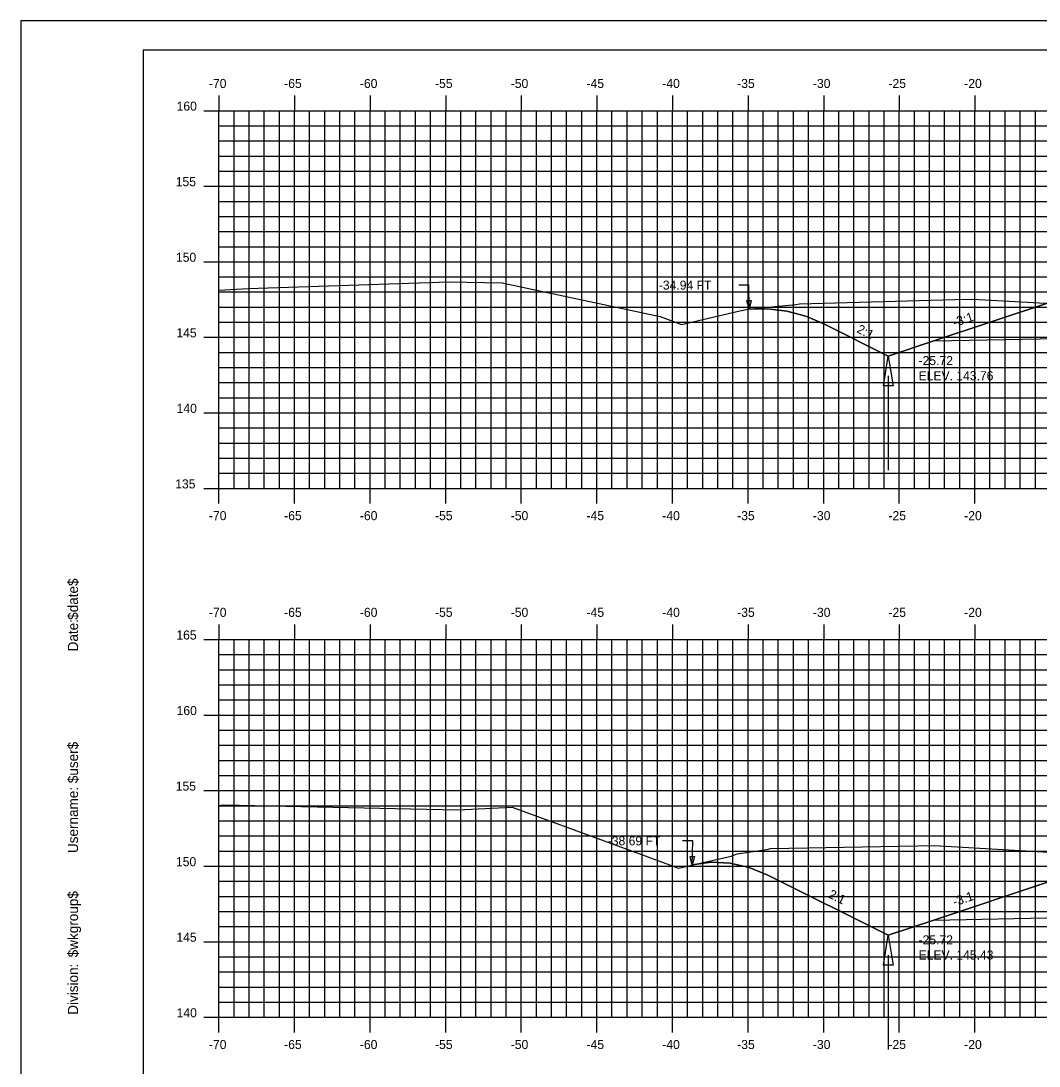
# Model space of a CAD drawing. Extents: x 1143642 to 1143812, y 608981 to 609091.
# Drawn here: x 1143641.7 to 1143709.1, y 609022.1 to 609091.3 of the extents above; entities that cross this region are included whole.
import ezdxf

# ---------------------------------------------------------------- set-up
doc = ezdxf.new("R2010")
doc.units = 0
for name, color, linetype in [('ANNOTATION', 7, 'Continuous'), ('BORDER', 7, 'Continuous'), ('D_Drainage_Ditch_Line', 7, 'Continuous'), ('D_Roadway_SlopeLines', 7, 'Continuous'), ('D_Roadway_SubGrade', 7, 'Continuous'), ('D_Text_Standard', 7, 'Continuous'), ('H_V ANNOTATION', 7, 'Continuous'), ('MAJOR', 7, 'Continuous'), ('MINOR', 7, 'Continuous'), ('PLOT BOUNDARY', 7, 'Continuous'), ('S_Roadway_Centerline', 7, 'Continuous')]:
    doc.layers.add(name, color=color, linetype=linetype)

msp = doc.modelspace()

# ---------------------------------------------------------------- linework, layer by layer
for points in [[(1143689.9, 609072.198), (1143691.15, 609072.231), (1143692.4, 609072.077), (1143693.65, 609071.734), (1143694.9, 609071.203), (1143699.112, 609069.097), (1143702.112, 609070.097), (1143709.835, 609072.671), (1143709.836, 609072.671), (1143713.836, 609072.831), (1143724.836, 609073.051), (1143735.836, 609072.831), (1143742.836, 609072.551), (1143750.368, 609070.041), (1143753.368, 609069.041), (1143766.479, 609075.596), (1143767.729, 609076.147), (1143768.979, 609076.547), (1143770.229, 609076.799), (1143771.479, 609076.901)], [(1143686.147, 609035.418), (1143687.397, 609035.592), (1143688.647, 609035.538), (1143689.897, 609035.255), (1143691.147, 609034.744), (1143699.112, 609030.762), (1143702.112, 609031.762), (1143709.835, 609034.336), (1143709.836, 609034.336), (1143713.836, 609034.496), (1143724.836, 609034.716), (1143735.836, 609034.496), (1143748.494, 609033.99), (1143755.665, 609031.599), (1143758.665, 609030.599), (1143776.249, 609039.391), (1143777.499, 609039.941), (1143778.749, 609040.338), (1143779.999, 609040.585), (1143781.249, 609040.679)]]:
    msp.add_lwpolyline(points)
at = {"layer": 'BORDER'}
msp.add_lwpolyline([(1143649.836, 608984.335), (1143809.836, 608984.335), (1143809.836, 609089.335), (1143649.836, 609089.335)], close=True, dxfattribs=at)
at = {"layer": 'D_Drainage_Ditch_Line'}
for p, q in [((1143699.112, 609067.785), (1143699.111, 609061.541)), ((1143699.112, 609029.449), (1143699.111, 609023.206))]:
    msp.add_line(p, q, dxfattribs=at)
for points in [[(1143699.44, 609067.128), (1143698.783, 609067.128), (1143699.112, 609069.097)], [(1143699.44, 609028.793), (1143698.783, 609028.793), (1143699.112, 609030.762)]]:
    msp.add_lwpolyline(points, close=True, dxfattribs=at)
at = {"layer": 'D_Roadway_SlopeLines'}
for points in [[(1143699.112, 609069.097), (1143694.9, 609071.203), (1143693.65, 609071.734), (1143692.4, 609072.077), (1143691.15, 609072.231), (1143689.9, 609072.198)], [(1143702.112, 609070.097), (1143699.112, 609069.097)], [(1143699.112, 609030.762), (1143691.147, 609034.744), (1143689.897, 609035.255), (1143688.647, 609035.538), (1143687.397, 609035.592), (1143686.147, 609035.418)], [(1143702.112, 609031.762), (1143699.112, 609030.762)]]:
    msp.add_lwpolyline(points, dxfattribs=at)
at = {"layer": 'D_Roadway_SubGrade'}
for points in [[(1143713.836, 609072.415), (1143713.836, 609072.581), (1143709.836, 609072.421), (1143709.836, 609072.671), (1143709.835, 609072.671), (1143702.112, 609070.097), (1143713.836, 609070.331)], [(1143713.836, 609034.079), (1143713.836, 609034.246), (1143709.836, 609034.086), (1143709.836, 609034.336), (1143709.835, 609034.336), (1143702.112, 609031.762), (1143713.836, 609031.996)]]:
    msp.add_lwpolyline(points, close=True, dxfattribs=at)
at = {"layer": 'D_Text_Standard'}
for points in [[(1143689.9, 609072.2), (1143689.896, 609073.789), (1143689.216, 609073.789)], [(1143686.147, 609035.397), (1143686.175, 609037.012), (1143685.495, 609037.012)]]:
    msp.add_lwpolyline(points, dxfattribs=at)
for points in [[(1143689.9, 609072.2), (1143689.753, 609072.782), (1143690.044, 609072.783)], [(1143686.147, 609035.397), (1143686.011, 609035.982), (1143686.302, 609035.977)]]:
    msp.add_lwpolyline(points, close=True, dxfattribs=at)
at = {"layer": 'MAJOR'}
for p, q in [((1143654.836, 609086.337), (1143654.836, 609085.335)), ((1143659.836, 609086.337), (1143659.836, 609085.335)), ((1143664.836, 609086.337), (1143664.836, 609085.335)), ((1143669.836, 609086.337), (1143669.836, 609085.335)), ((1143674.836, 609086.337), (1143674.836, 609085.335)), ((1143679.836, 609086.337), (1143679.836, 609085.335)), ((1143684.836, 609086.337), (1143684.836, 609085.335)), ((1143689.836, 609086.337), (1143689.836, 609085.335)), ((1143694.836, 609086.337), (1143694.836, 609085.335)), ((1143699.836, 609086.337), (1143699.836, 609085.335)), ((1143704.836, 609086.337), (1143704.836, 609085.335)), ((1143653.834, 609085.335), (1143654.836, 609085.335)), ((1143654.836, 609085.335), (1143794.836, 609085.335)), ((1143654.836, 609060.335), (1143654.836, 609085.335)), ((1143654.836, 609060.335), (1143654.836, 609085.335)), ((1143654.836, 609085.335), (1143794.836, 609085.335)), ((1143659.836, 609060.335), (1143659.836, 609085.335)), ((1143664.836, 609060.335), (1143664.836, 609085.335)), ((1143669.836, 609060.335), (1143669.836, 609085.335)), ((1143674.836, 609060.335), (1143674.836, 609085.335)), ((1143679.836, 609060.335), (1143679.836, 609085.335)), ((1143684.836, 609060.335), (1143684.836, 609085.335)), ((1143689.836, 609060.335), (1143689.836, 609085.335)), ((1143694.836, 609060.335), (1143694.836, 609085.335)), ((1143699.836, 609060.335), (1143699.836, 609085.335)), ((1143704.836, 609060.335), (1143704.836, 609085.335)), ((1143653.834, 609080.335), (1143654.836, 609080.335)), ((1143654.836, 609080.335), (1143794.836, 609080.335)), ((1143653.834, 609075.335), (1143654.836, 609075.335)), ((1143654.836, 609075.335), (1143794.836, 609075.335)), ((1143653.834, 609070.335), (1143654.836, 609070.335)), ((1143654.836, 609070.335), (1143794.836, 609070.335)), ((1143653.834, 609065.335), (1143654.836, 609065.335)), ((1143654.836, 609065.335), (1143794.836, 609065.335)), ((1143653.834, 609060.335), (1143654.836, 609060.335)), ((1143654.836, 609060.335), (1143794.836, 609060.335)), ((1143654.836, 609060.335), (1143794.836, 609060.335)), ((1143654.836, 609059.333), (1143654.836, 609060.335)), ((1143659.836, 609059.333), (1143659.836, 609060.335)), ((1143664.836, 609059.333), (1143664.836, 609060.335)), ((1143669.836, 609059.333), (1143669.836, 609060.335)), ((1143674.836, 609059.333), (1143674.836, 609060.335)), ((1143679.836, 609059.333), (1143679.836, 609060.335)), ((1143684.836, 609059.333), (1143684.836, 609060.335)), ((1143689.836, 609059.333), (1143689.836, 609060.335)), ((1143694.836, 609059.333), (1143694.836, 609060.335)), ((1143699.836, 609059.333), (1143699.836, 609060.335)), ((1143704.836, 609059.333), (1143704.836, 609060.335)), ((1143654.836, 609051.337), (1143654.836, 609050.335)), ((1143659.836, 609051.337), (1143659.836, 609050.335)), ((1143664.836, 609051.337), (1143664.836, 609050.335)), ((1143669.836, 609051.337), (1143669.836, 609050.335)), ((1143674.836, 609051.337), (1143674.836, 609050.335)), ((1143679.836, 609051.337), (1143679.836, 609050.335)), ((1143684.836, 609051.337), (1143684.836, 609050.335)), ((1143689.836, 609051.337), (1143689.836, 609050.335)), ((1143694.836, 609051.337), (1143694.836, 609050.335)), ((1143699.836, 609051.337), (1143699.836, 609050.335)), ((1143704.836, 609051.337), (1143704.836, 609050.335)), ((1143653.834, 609050.335), (1143654.836, 609050.335)), ((1143654.836, 609050.335), (1143794.836, 609050.335)), ((1143654.836, 609025.335), (1143654.836, 609050.335)), ((1143654.836, 609025.335), (1143654.836, 609050.335)), ((1143654.836, 609050.335), (1143794.836, 609050.335)), ((1143659.836, 609025.335), (1143659.836, 609050.335)), ((1143664.836, 609025.335), (1143664.836, 609050.335)), ((1143669.836, 609025.335), (1143669.836, 609050.335)), ((1143674.836, 609025.335), (1143674.836, 609050.335)), ((1143679.836, 609025.335), (1143679.836, 609050.335)), ((1143684.836, 609025.335), (1143684.836, 609050.335)), ((1143689.836, 609025.335), (1143689.836, 609050.335)), ((1143694.836, 609025.335), (1143694.836, 609050.335)), ((1143699.836, 609025.335), (1143699.836, 609050.335)), ((1143704.836, 609025.335), (1143704.836, 609050.335)), ((1143653.834, 609045.335), (1143654.836, 609045.335)), ((1143654.836, 609045.335), (1143794.836, 609045.335)), ((1143653.834, 609040.335), (1143654.836, 609040.335)), ((1143654.836, 609040.335), (1143794.836, 609040.335)), ((1143653.834, 609035.335), (1143654.836, 609035.335)), ((1143654.836, 609035.335), (1143794.836, 609035.335)), ((1143653.834, 609030.335), (1143654.836, 609030.335)), ((1143654.836, 609030.335), (1143794.836, 609030.335)), ((1143653.834, 609025.335), (1143654.836, 609025.335)), ((1143654.836, 609025.335), (1143794.836, 609025.335)), ((1143654.836, 609025.335), (1143794.836, 609025.335)), ((1143654.836, 609024.333), (1143654.836, 609025.335)), ((1143659.836, 609024.333), (1143659.836, 609025.335)), ((1143664.836, 609024.333), (1143664.836, 609025.335)), ((1143669.836, 609024.333), (1143669.836, 609025.335)), ((1143674.836, 609024.333), (1143674.836, 609025.335)), ((1143679.836, 609024.333), (1143679.836, 609025.335)), ((1143684.836, 609024.333), (1143684.836, 609025.335)), ((1143689.836, 609024.333), (1143689.836, 609025.335)), ((1143694.836, 609024.333), (1143694.836, 609025.335)), ((1143699.836, 609024.333), (1143699.836, 609025.335)), ((1143704.836, 609024.333), (1143704.836, 609025.335))]:
    msp.add_line(p, q, dxfattribs=at)
at = {"layer": 'MINOR'}
for p, q in [((1143655.836, 609060.335), (1143655.836, 609085.335)), ((1143656.836, 609060.335), (1143656.836, 609085.335)), ((1143657.836, 609060.335), (1143657.836, 609085.335)), ((1143658.836, 609060.335), (1143658.836, 609085.335)), ((1143660.836, 609060.335), (1143660.836, 609085.335)), ((1143661.836, 609060.335), (1143661.836, 609085.335)), ((1143662.836, 609060.335), (1143662.836, 609085.335)), ((1143663.836, 609060.335), (1143663.836, 609085.335)), ((1143665.836, 609060.335), (1143665.836, 609085.335)), ((1143666.836, 609060.335), (1143666.836, 609085.335)), ((1143667.836, 609060.335), (1143667.836, 609085.335)), ((1143668.836, 609060.335), (1143668.836, 609085.335)), ((1143670.836, 609060.335), (1143670.836, 609085.335)), ((1143671.836, 609060.335), (1143671.836, 609085.335)), ((1143672.836, 609060.335), (1143672.836, 609085.335)), ((1143673.836, 609060.335), (1143673.836, 609085.335)), ((1143675.836, 609060.335), (1143675.836, 609085.335)), ((1143676.836, 609060.335), (1143676.836, 609085.335)), ((1143677.836, 609060.335), (1143677.836, 609085.335)), ((1143678.836, 609060.335), (1143678.836, 609085.335)), ((1143680.836, 609060.335), (1143680.836, 609085.335)), ((1143681.836, 609060.335), (1143681.836, 609085.335)), ((1143682.836, 609060.335), (1143682.836, 609085.335)), ((1143683.836, 609060.335), (1143683.836, 609085.335)), ((1143685.836, 609060.335), (1143685.836, 609085.335)), ((1143686.836, 609060.335), (1143686.836, 609085.335)), ((1143687.836, 609060.335), (1143687.836, 609085.335)), ((1143688.836, 609060.335), (1143688.836, 609085.335)), ((1143690.836, 609060.335), (1143690.836, 609085.335)), ((1143691.836, 609060.335), (1143691.836, 609085.335)), ((1143692.836, 609060.335), (1143692.836, 609085.335)), ((1143693.836, 609060.335), (1143693.836, 609085.335)), ((1143695.836, 609060.335), (1143695.836, 609085.335)), ((1143696.836, 609060.335), (1143696.836, 609085.335)), ((1143697.836, 609060.335), (1143697.836, 609085.335)), ((1143698.836, 609060.335), (1143698.836, 609085.335)), ((1143700.836, 609060.335), (1143700.836, 609085.335)), ((1143701.836, 609060.335), (1143701.836, 609085.335)), ((1143702.836, 609060.335), (1143702.836, 609085.335)), ((1143703.836, 609060.335), (1143703.836, 609085.335)), ((1143705.836, 609060.335), (1143705.836, 609085.335)), ((1143706.836, 609060.335), (1143706.836, 609085.335)), ((1143707.836, 609060.335), (1143707.836, 609085.335)), ((1143708.836, 609060.335), (1143708.836, 609085.335)), ((1143654.836, 609084.335), (1143794.836, 609084.335)), ((1143654.836, 609084.335), (1143655.838, 609084.335)), ((1143654.836, 609083.335), (1143794.836, 609083.335)), ((1143654.836, 609083.335), (1143655.838, 609083.335)), ((1143654.836, 609082.335), (1143794.836, 609082.335)), ((1143654.836, 609082.335), (1143655.838, 609082.335)), ((1143654.836, 609081.335), (1143794.836, 609081.335)), ((1143654.836, 609081.335), (1143655.838, 609081.335)), ((1143654.836, 609079.335), (1143794.836, 609079.335)), ((1143654.836, 609079.335), (1143655.838, 609079.335)), ((1143654.836, 609078.335), (1143794.836, 609078.335)), ((1143654.836, 609078.335), (1143655.838, 609078.335)), ((1143654.836, 609077.335), (1143794.836, 609077.335)), ((1143654.836, 609077.335), (1143655.838, 609077.335)), ((1143654.836, 609076.335), (1143794.836, 609076.335)), ((1143654.836, 609076.335), (1143655.838, 609076.335)), ((1143654.836, 609074.335), (1143794.836, 609074.335)), ((1143654.836, 609074.335), (1143655.838, 609074.335)), ((1143654.836, 609073.335), (1143794.836, 609073.335)), ((1143654.836, 609073.335), (1143655.838, 609073.335)), ((1143654.836, 609072.335), (1143794.836, 609072.335)), ((1143654.836, 609072.335), (1143655.838, 609072.335)), ((1143654.836, 609071.335), (1143794.836, 609071.335)), ((1143654.836, 609071.335), (1143655.838, 609071.335)), ((1143654.836, 609069.335), (1143794.836, 609069.335)), ((1143654.836, 609069.335), (1143655.838, 609069.335)), ((1143654.836, 609068.335), (1143794.836, 609068.335)), ((1143654.836, 609068.335), (1143655.838, 609068.335)), ((1143654.836, 609067.335), (1143794.836, 609067.335)), ((1143654.836, 609067.335), (1143655.838, 609067.335)), ((1143654.836, 609066.335), (1143794.836, 609066.335)), ((1143654.836, 609066.335), (1143655.838, 609066.335)), ((1143654.836, 609064.335), (1143794.836, 609064.335)), ((1143654.836, 609064.335), (1143655.838, 609064.335)), ((1143654.836, 609063.335), (1143794.836, 609063.335)), ((1143654.836, 609063.335), (1143655.838, 609063.335)), ((1143654.836, 609062.335), (1143794.836, 609062.335)), ((1143654.836, 609062.335), (1143655.838, 609062.335)), ((1143654.836, 609061.335), (1143794.836, 609061.335)), ((1143654.836, 609061.335), (1143655.838, 609061.335)), ((1143655.836, 609025.335), (1143655.836, 609050.335)), ((1143656.836, 609025.335), (1143656.836, 609050.335)), ((1143657.836, 609025.335), (1143657.836, 609050.335)), ((1143658.836, 609025.335), (1143658.836, 609050.335)), ((1143660.836, 609025.335), (1143660.836, 609050.335)), ((1143661.836, 609025.335), (1143661.836, 609050.335)), ((1143662.836, 609025.335), (1143662.836, 609050.335)), ((1143663.836, 609025.335), (1143663.836, 609050.335)), ((1143665.836, 609025.335), (1143665.836, 609050.335)), ((1143666.836, 609025.335), (1143666.836, 609050.335)), ((1143667.836, 609025.335), (1143667.836, 609050.335)), ((1143668.836, 609025.335), (1143668.836, 609050.335)), ((1143670.836, 609025.335), (1143670.836, 609050.335)), ((1143671.836, 609025.335), (1143671.836, 609050.335)), ((1143672.836, 609025.335), (1143672.836, 609050.335)), ((1143673.836, 609025.335), (1143673.836, 609050.335)), ((1143675.836, 609025.335), (1143675.836, 609050.335)), ((1143676.836, 609025.335), (1143676.836, 609050.335)), ((1143677.836, 609025.335), (1143677.836, 609050.335)), ((1143678.836, 609025.335), (1143678.836, 609050.335)), ((1143680.836, 609025.335), (1143680.836, 609050.335)), ((1143681.836, 609025.335), (1143681.836, 609050.335)), ((1143682.836, 609025.335), (1143682.836, 609050.335)), ((1143683.836, 609025.335), (1143683.836, 609050.335)), ((1143685.836, 609025.335), (1143685.836, 609050.335)), ((1143686.836, 609025.335), (1143686.836, 609050.335)), ((1143687.836, 609025.335), (1143687.836, 609050.335)), ((1143688.836, 609025.335), (1143688.836, 609050.335)), ((1143690.836, 609025.335), (1143690.836, 609050.335)), ((1143691.836, 609025.335), (1143691.836, 609050.335)), ((1143692.836, 609025.335), (1143692.836, 609050.335)), ((1143693.836, 609025.335), (1143693.836, 609050.335)), ((1143695.836, 609025.335), (1143695.836, 609050.335)), ((1143696.836, 609025.335), (1143696.836, 609050.335)), ((1143697.836, 609025.335), (1143697.836, 609050.335)), ((1143698.836, 609025.335), (1143698.836, 609050.335)), ((1143700.836, 609025.335), (1143700.836, 609050.335)), ((1143701.836, 609025.335), (1143701.836, 609050.335)), ((1143702.836, 609025.335), (1143702.836, 609050.335)), ((1143703.836, 609025.335), (1143703.836, 609050.335)), ((1143705.836, 609025.335), (1143705.836, 609050.335)), ((1143706.836, 609025.335), (1143706.836, 609050.335)), ((1143707.836, 609025.335), (1143707.836, 609050.335)), ((1143708.836, 609025.335), (1143708.836, 609050.335)), ((1143654.836, 609049.335), (1143794.836, 609049.335)), ((1143654.836, 609049.335), (1143655.838, 609049.335)), ((1143654.836, 609048.335), (1143794.836, 609048.335)), ((1143654.836, 609048.335), (1143655.838, 609048.335)), ((1143654.836, 609047.335), (1143794.836, 609047.335)), ((1143654.836, 609047.335), (1143655.838, 609047.335)), ((1143654.836, 609046.335), (1143794.836, 609046.335)), ((1143654.836, 609046.335), (1143655.838, 609046.335)), ((1143654.836, 609044.335), (1143794.836, 609044.335)), ((1143654.836, 609044.335), (1143655.838, 609044.335)), ((1143654.836, 609043.335), (1143794.836, 609043.335)), ((1143654.836, 609043.335), (1143655.838, 609043.335)), ((1143654.836, 609042.335), (1143794.836, 609042.335)), ((1143654.836, 609042.335), (1143655.838, 609042.335)), ((1143654.836, 609041.335), (1143794.836, 609041.335)), ((1143654.836, 609041.335), (1143655.838, 609041.335)), ((1143654.836, 609039.335), (1143794.836, 609039.335)), ((1143654.836, 609039.335), (1143655.838, 609039.335)), ((1143654.836, 609038.335), (1143794.836, 609038.335)), ((1143654.836, 609038.335), (1143655.838, 609038.335)), ((1143654.836, 609037.335), (1143794.836, 609037.335)), ((1143654.836, 609037.335), (1143655.838, 609037.335)), ((1143654.836, 609036.335), (1143794.836, 609036.335)), ((1143654.836, 609036.335), (1143655.838, 609036.335)), ((1143654.836, 609034.335), (1143794.836, 609034.335)), ((1143654.836, 609034.335), (1143655.838, 609034.335)), ((1143654.836, 609033.335), (1143794.836, 609033.335)), ((1143654.836, 609033.335), (1143655.838, 609033.335)), ((1143654.836, 609032.335), (1143794.836, 609032.335)), ((1143654.836, 609032.335), (1143655.838, 609032.335)), ((1143654.836, 609031.335), (1143794.836, 609031.335)), ((1143654.836, 609031.335), (1143655.838, 609031.335)), ((1143654.836, 609029.335), (1143794.836, 609029.335)), ((1143654.836, 609029.335), (1143655.838, 609029.335)), ((1143654.836, 609028.335), (1143794.836, 609028.335)), ((1143654.836, 609028.335), (1143655.838, 609028.335)), ((1143654.836, 609027.335), (1143794.836, 609027.335)), ((1143654.836, 609027.335), (1143655.838, 609027.335)), ((1143654.836, 609026.335), (1143794.836, 609026.335)), ((1143654.836, 609026.335), (1143655.838, 609026.335))]:
    msp.add_line(p, q, dxfattribs=at)
at = {"layer": 'PLOT BOUNDARY'}
msp.add_lwpolyline([(1143641.743, 608981.276), (1143811.743, 608981.276), (1143811.743, 609091.276), (1143641.743, 609091.276)], close=True, dxfattribs=at)
at = {"layer": 'S_Roadway_Centerline'}
for points in [[(1143654.836, 609073.452), (1143656.779, 609073.558), (1143670.077, 609074.012), (1143673.562, 609073.936), (1143684.029, 609071.706), (1143685.439, 609071.188), (1143689.293, 609072.087), (1143689.817, 609072.189), (1143692.998, 609072.514), (1143693.234, 609072.55), (1143703.514, 609072.846), (1143704.706, 609072.868), (1143705.911, 609072.799), (1143715.089, 609072.281), (1143715.529, 609072.252), (1143719.31, 609071.914), (1143720.106, 609071.688), (1143723.487, 609070.975), (1143725.236, 609072.046), (1143730.481, 609074.786), (1143737.909, 609075.389), (1143759.635, 609076.642), (1143794.836, 609077.413)], [(1143654.836, 609039.36), (1143655.137, 609039.396), (1143670.63, 609039.062), (1143674.234, 609039.237), (1143682.779, 609036.11), (1143685.235, 609035.209), (1143688.71, 609036.009), (1143689.113, 609036.145), (1143691.075, 609036.45), (1143691.321, 609036.505), (1143701.057, 609036.688), (1143702.154, 609036.699), (1143712.738, 609036.093)]]:
    msp.add_lwpolyline(points, dxfattribs=at)

# ---------------------------------------------------------------- texts
at = {"layer": 'ANNOTATION'}
for s, rotation, p in [('-3:1', 18.43482, (1143703.491, 609071.011)), ('2:1', 333.43495, (1143696.973, 609070.684)), ('2:1', 333.43495, (1143695.096, 609033.287)), ('-3:1', 18.43482, (1143703.491, 609032.675))]:
    msp.add_text(s, height=0.6, rotation=rotation, dxfattribs=at).set_placement(p)
at = {"layer": 'BORDER'}
for s, p in [('$date$', (1143645.521, 609051.64)), ('Date:', (1143645.521, 609049.552)), ('$user$', (1143645.521, 609040.827)), ('Username:', (1143645.521, 609036.203)), ('$wkgroup$', (1143645.521, 609029.305)), ('Division:', (1143645.521, 609025.501))]:
    msp.add_text(s, height=0.6696, rotation=90, dxfattribs=at).set_placement(p)
at = {"layer": 'D_Text_Standard'}
for s, p in [('-34.94 FT', (1143683.933, 609073.489)), ('-25.72', (1143701.112, 609068.497)), ('ELEV. 143.76', (1143701.112, 609067.495)), ('-38.69 FT', (1143680.555, 609036.712)), ('-25.72', (1143701.112, 609030.162)), ('ELEV. 145.43', (1143701.112, 609029.16))]:
    msp.add_text(s, height=0.6, dxfattribs=at).set_placement(p)
at = {"layer": 'H_V ANNOTATION'}
for s, p in [('-70', (1143654.178, 609086.835)), ('-65', (1143659.154, 609086.835)), ('-60', (1143664.162, 609086.835)), ('-55', (1143669.132, 609086.835)), ('-50', (1143674.14, 609086.835)), ('-45', (1143679.154, 609086.835)), ('-40', (1143684.162, 609086.835)), ('-35', (1143689.116, 609086.835)), ('-30', (1143694.124, 609086.835)), ('-25', (1143699.122, 609086.835)), ('-20', (1143704.13, 609086.835)), ('160', (1143652.041, 609085.335)), ('155', (1143651.982, 609080.335)), ('150', (1143651.998, 609075.335)), ('145', (1143652.025, 609070.335)), ('140', (1143652.041, 609065.335)), ('135', (1143651.95, 609060.335)), ('-70', (1143654.178, 609058.235)), ('-65', (1143659.154, 609058.235)), ('-60', (1143664.162, 609058.235)), ('-55', (1143669.132, 609058.235)), ('-50', (1143674.14, 609058.235)), ('-45', (1143679.154, 609058.235)), ('-40', (1143684.162, 609058.235)), ('-35', (1143689.116, 609058.235)), ('-30', (1143694.124, 609058.235)), ('-25', (1143699.122, 609058.235)), ('-20', (1143704.13, 609058.235)), ('-70', (1143654.178, 609051.835)), ('-65', (1143659.154, 609051.835)), ('-60', (1143664.162, 609051.835)), ('-55', (1143669.132, 609051.835)), ('-50', (1143674.14, 609051.835)), ('-45', (1143679.154, 609051.835)), ('-40', (1143684.162, 609051.835)), ('-35', (1143689.116, 609051.835)), ('-30', (1143694.124, 609051.835)), ('-25', (1143699.122, 609051.835)), ('-20', (1143704.13, 609051.835)), ('165', (1143652.025, 609050.335)), ('160', (1143652.041, 609045.335)), ('155', (1143651.982, 609040.335)), ('150', (1143651.998, 609035.335)), ('145', (1143652.025, 609030.335)), ('140', (1143652.041, 609025.335)), ('-70', (1143654.178, 609023.235)), ('-65', (1143659.154, 609023.235)), ('-60', (1143664.162, 609023.235)), ('-55', (1143669.132, 609023.235)), ('-50', (1143674.14, 609023.235)), ('-45', (1143679.154, 609023.235)), ('-40', (1143684.162, 609023.235)), ('-35', (1143689.116, 609023.235)), ('-30', (1143694.124, 609023.235)), ('-25', (1143699.122, 609023.235)), ('-20', (1143704.13, 609023.235))]:
    msp.add_text(s, height=0.6, dxfattribs=at).set_placement(p)
at = {"layer": 'MAJOR'}
for p in [(1143654.832, 609060.335), (1143654.832, 609025.335)]:
    msp.add_text('-', height=0.006, dxfattribs=at).set_placement(p)
at = {"layer": 'S_Roadway_Centerline'}
for s, p in [('L', (1143704.698, 609072.861)), ('C', (1143704.701, 609072.868)), ('L', (1143702.145, 609036.692)), ('C', (1143702.148, 609036.699))]:
    msp.add_text(s, height=0.0146, dxfattribs=at).set_placement(p)

doc.saveas('drawing.dxf')
